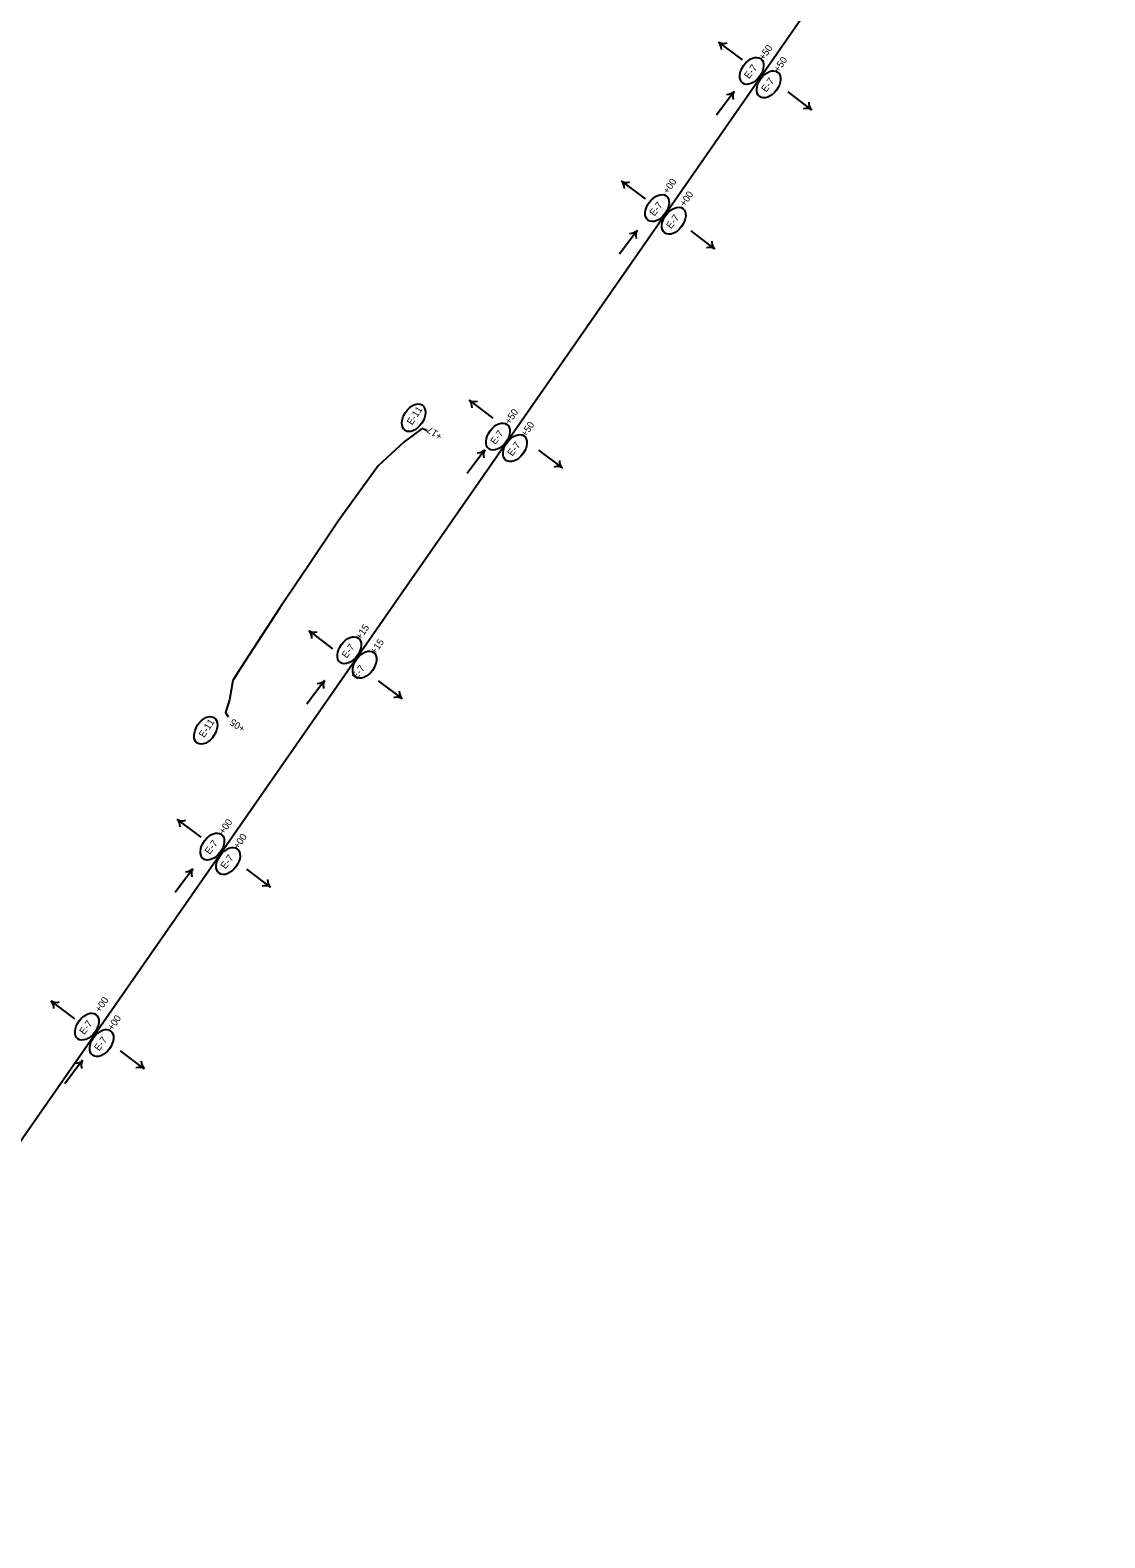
# Model space of a CAD drawing. Extents: x 669236 to 673912, y 735758 to 754788.
# Drawn here: x 672475 to 673441, y 746819 to 748174 of the extents above; entities that cross this region are included whole.
import ezdxf

# ---------------------------------------------------------------- set-up
doc = ezdxf.new("R2010")
doc.units = 0
for name, color, linetype in [('Default', 7, 'Continuous'), ('R_Erosion_2', 7, 'Continuous'), ('R_Erosion_3', 7, 'Continuous'), ('R_Flow Arrows', 7, 'Continuous')]:
    doc.layers.add(name, color=color, linetype=linetype)

msp = doc.modelspace()

# ---------------------------------------------------------------- linework, layer by layer
at = {"layer": 'Default'}
msp.add_line((671572, 745891.2), (673440.9, 748577.2), dxfattribs=at)
at = {"layer": 'R_Erosion_2'}
for centre in [(673123.4, 748137.9), (673138.6, 748125.8), (673038.3, 748014.5), (673053.3, 748003.1), (672895.2, 747809.1), (672910.5, 747798.7), (672761.5, 747617), (672775.3, 747604), (672638.4, 747440.5), (672652.6, 747427.5), (672525.6, 747278.6), (672538.8, 747263.9)]:
    msp.add_ellipse(centre, major_axis=(8.1, 11), ratio=0.638788, dxfattribs=at)
at = {"layer": 'R_Erosion_3'}
msp.add_lwpolyline([(672831.6, 747814.3), (672827, 747816.3), (672811, 747804.5), (672787.5, 747782.9), (672751.6, 747733.1), (672724.8, 747693.3), (672699, 747655.1), (672663.5, 747600.4), (672656.7, 747589.7), (672653.8, 747572.3), (672650.1, 747561.1), (672652.7, 747557.1)], dxfattribs=at)
for centre in [(672819.4, 747826), (672632.5, 747545)]:
    msp.add_ellipse(centre, major_axis=(7.5, 11.5), ratio=0.638788, dxfattribs=at)
at = {"layer": 'R_Flow Arrows'}
for p, q in [((673093.6, 748163.8), (673114.7, 748147.7)), ((673107.5, 748119.4), (673091.6, 748098.1)), ((673177.2, 748103), (673156.1, 748119.1)), ((673006.3, 748038.8), (673027.5, 748022.7)), ((673020.3, 747994.4), (673004.4, 747973.2)), ((673090, 747978), (673068.9, 747994.1)), ((672869.4, 747841.7), (672890.6, 747825.6)), ((672883.4, 747797.3), (672867.5, 747776)), ((672953.1, 747780.9), (672931.9, 747797)), ((672725.4, 747634.3), (672746.5, 747618.2)), ((672739.3, 747589.9), (672723.4, 747568.6)), ((672809, 747573.5), (672787.9, 747589.6)), ((672606.9, 747464.9), (672628, 747448.8)), ((672620.9, 747420.5), (672604.9, 747399.2)), ((672690.6, 747404.1), (672669.4, 747420.2)), ((672493.4, 747301.6), (672514.5, 747285.5)), ((672521.7, 747248.3), (672505.8, 747227.1)), ((672577, 747240.8), (672555.9, 747256.9))]:
    msp.add_line(p, q, dxfattribs=at)
for centre, major_axis, start_param, end_param in [((673081, 748148), (12.2, 16), 5.662936, 6.259934), ((673105.6, 748180), (-12.2, -16), 0.023252, 0.620249), ((673091.6, 748131.8), (16.1, -12.1), 5.662936, 6.259934), ((673123.8, 748107.5), (-16.1, 12.1), 0.023252, 0.620249), ((673165.2, 748086.8), (12.2, 16), 0.023252, 0.620249), ((673189.8, 748118.7), (-12.2, -16), 5.662936, 6.259934), ((672993.8, 748023.1), (12.2, 16), 5.662936, 6.259934), ((673018.3, 748055), (-12.2, -16), 0.023252, 0.620249), ((673004.4, 748006.9), (16.1, -12.1), 5.662936, 6.259934), ((673036.6, 747982.6), (-16.1, 12.1), 0.023252, 0.620249), ((673078, 747961.8), (12.2, 16), 0.023252, 0.620249), ((673102.6, 747993.8), (-12.2, -16), 5.662936, 6.259934), ((672856.9, 747825.9), (12.2, 16), 5.662936, 6.259934), ((672881.4, 747857.9), (-12.2, -16), 0.023252, 0.620249), ((672867.5, 747809.7), (16.1, -12.1), 5.662936, 6.259934), ((672899.7, 747785.4), (-16.1, 12.1), 0.023252, 0.620249), ((672965.6, 747796.6), (-12.2, -16), 5.662936, 6.259934), ((672941.1, 747764.7), (12.2, 16), 0.023252, 0.620249), ((672712.8, 747618.5), (12.2, 16), 5.662936, 6.259934), ((672737.4, 747650.5), (-12.2, -16), 0.023252, 0.620249), ((672723.5, 747602.3), (16.1, -12.1), 5.662936, 6.259934), ((672755.6, 747578), (-16.1, 12.1), 0.023252, 0.620249), ((672797, 747557.3), (12.2, 16), 0.023252, 0.620249), ((672821.6, 747589.2), (-12.2, -16), 5.662936, 6.259934), ((672594.3, 747449.1), (12.2, 16), 5.662936, 6.259934), ((672618.9, 747481.1), (-12.2, -16), 0.023252, 0.620249), ((672605, 747432.9), (16.1, -12.1), 5.662936, 6.259934), ((672637.1, 747408.6), (-16.1, 12.1), 0.023252, 0.620249), ((672703.1, 747419.8), (-12.2, -16), 5.662936, 6.259934), ((672678.6, 747387.9), (12.2, 16), 0.023252, 0.620249), ((672480.8, 747285.8), (12.2, 16), 5.662936, 6.259934), ((672505.4, 747317.8), (-12.2, -16), 0.023252, 0.620249), ((672505.9, 747260.8), (16.1, -12.1), 5.662936, 6.259934), ((672538, 747236.5), (-16.1, 12.1), 0.023252, 0.620249), ((672589.6, 747256.6), (-12.2, -16), 5.662936, 6.259934), ((672565, 747224.6), (12.2, 16), 0.023252, 0.620249)]:
    msp.add_ellipse(centre, major_axis=major_axis, ratio=0.5625, start_param=start_param, end_param=end_param, dxfattribs=at)

# ---------------------------------------------------------------- texts
at = {"layer": 'R_Erosion_2'}
for s, rotation, p in [('+50', 55.5768, (673134.4, 748146.9)), ('E-7', 53.5441, (673121, 748130.2)), ('+50', 55.5768, (673147.7, 748136.1)), ('E-7', 53.5441, (673136.3, 748118.2)), ('+00', 55.5768, (673048.1, 748026.7)), ('E-7', 53.5441, (673035.9, 748006.8)), ('+00', 55.5768, (673063.2, 748015.3)), ('E-7', 53.5441, (673050.9, 747995.4)), ('+50', 55.5768, (672905.8, 747819.6)), ('E-7', 53.5441, (672892.8, 747801.4)), ('+50', 55.5768, (672920.3, 747808.2)), ('E-7', 53.5441, (672908.1, 747791)), ('+15', 55.5768, (672771.8, 747625.8)), ('E-7', 53.5441, (672759.1, 747609.3)), ('+15', 55.5768, (672785.1, 747612.8)), ('E-7', 53.5441, (672768.3, 747590.2)), ('+00', 55.5768, (672648.8, 747450.9)), ('+00', 55.5768, (672661.8, 747437.7)), ('E-7', 53.5441, (672636, 747432.9)), ('E-7', 53.5441, (672650.2, 747419.8)), ('+00', 55.5768, (672537.4, 747290.9)), ('E-7', 53.5441, (672523.2, 747270.9)), ('+00', 55.5768, (672548.7, 747274.6)), ('E-7', 53.5441, (672536.5, 747256.2))]:
    msp.add_text(s, height=6.25, rotation=rotation, dxfattribs=at).set_placement(p)
at = {"layer": 'R_Erosion_3'}
for s, rotation, p in [('E-11', 56.9613, (672818, 747818.9)), ('+17', 146.1843, (672845.8, 747810.7)), ('E-11', 56.9613, (672631, 747537.9)), ('+05', 146.1843, (672668.6, 747547.9))]:
    msp.add_text(s, height=6.25, rotation=rotation, dxfattribs=at).set_placement(p)

doc.saveas('drawing.dxf')
